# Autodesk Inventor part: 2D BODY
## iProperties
Category: PART
Company: Cross Bros.
Shininess: 64.0
Length Units: 11272
Angle Units: 11279
Time Units: 11290
Mass Units: 11286
Length Display Precision: 3
Angle Display Precision: 2
Compacted: True
Part Number: 2D BODY
Document SubType Name: Modeling
Created: 2003-03
Designer: MVF
Catalog Web Link: www.crossbros.com
Density: 0.0
Volumn: 0.0
Area: 0.0
PropertySet Name: Model Information
Control State: 0
Master: False
Checked Out: False
HAND_LEN: 8,580 in
ELBOW_TO_WRIST: 10,920 in
SHOULDER_TO_ELBOW: 10,920 in
FOOT_LEN: 11,700 in
KNEE_TO_FOOT: 21,840 in
PELVIS_TO_KNEE: 17,160 in
PELVIS_WD: 15,600 in
SHOULDER_WD: 19,500 in
TORSO_HT: 26,130 in
HEAD_HT: 11,700 in
HEIGHT: 78,000 in
HEAD_JAW_WD: 5,897 in
HEAD_TOP_WD: 8,190 in
NECK_HT: 1,170 in
TORSO_BOT_THK: 7,625 in
ANKLE_THK: 4,003 in
SHOULDER_THK: 5,831 in
WRIST_THK: 2,624 in
TORSO_TOP_THK: 8,970 in
ELBOW_THK: 3,498 in
KNEE_THK: 5,337 in
HAND_THK: 1,574 in
LEG_TOP_THK: 7,625 in
Author: MVF
Title: iMike
